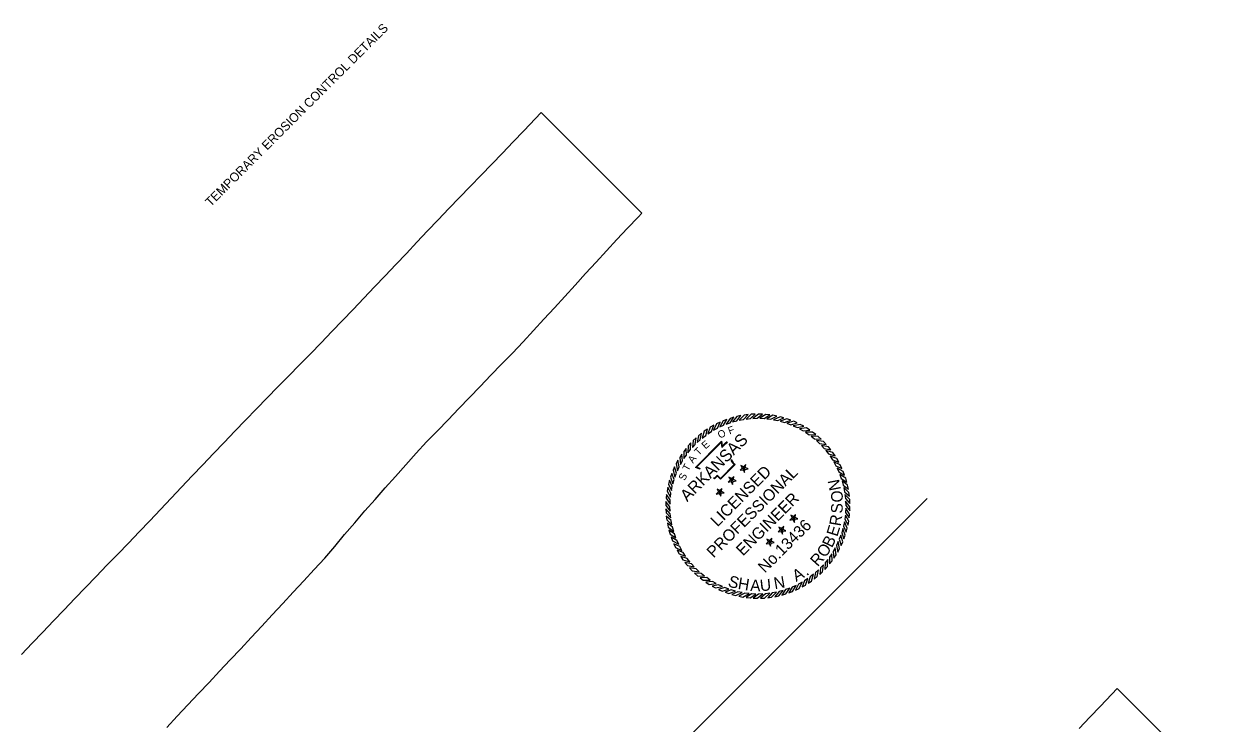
# Model space of a CAD drawing. Extents: x 1388120 to 1389841, y 1944102 to 1945760.
# Drawn here: x 1388980 to 1389753, y 1945307 to 1945760 of the extents above; entities that cross this region are included whole.
import ezdxf

# ---------------------------------------------------------------- set-up
doc = ezdxf.new("R2010")
doc.units = 0
for name, color, linetype in [('1', 7, 'Continuous'), ('G-ANNO-SYMB', 7, 'Continuous'), ('R_NO PLOT', 7, 'Continuous')]:
    doc.layers.add(name, color=color, linetype=linetype)

msp = doc.modelspace()

# ---------------------------------------------------------------- linework, layer by layer
at = {"layer": '1'}
msp.add_line((1389352.45, 1945239.6), (1389565.28, 1945452.44), dxfattribs=at)
at = {"layer": 'G-ANNO-SYMB'}
for points in [[(1389435.62, 1945503.65), (1389433.22, 1945502.74), (1389430.97, 1945498.76), (1389433.49, 1945499.9)], [(1389440.09, 1945505.05), (1389437.63, 1945504.33), (1389435.07, 1945500.54), (1389437.68, 1945501.48)], [(1389444.65, 1945506.1), (1389442.14, 1945505.57), (1389439.3, 1945501.99), (1389441.97, 1945502.72)], [(1389449.29, 1945506.78), (1389446.74, 1945506.45), (1389443.63, 1945503.11), (1389446.35, 1945503.63)], [(1389453.96, 1945507.1), (1389451.4, 1945506.97), (1389448.03, 1945503.88), (1389450.78, 1945504.18)], [(1389458.65, 1945507.05), (1389456.08, 1945507.12), (1389452.48, 1945504.3), (1389455.25, 1945504.39)], [(1389463.31, 1945506.63), (1389460.76, 1945506.9), (1389456.95, 1945504.38), (1389459.72, 1945504.25)], [(1389467.93, 1945505.85), (1389465.41, 1945506.32), (1389461.41, 1945504.1), (1389464.16, 1945503.76)], [(1389472.47, 1945504.7), (1389470, 1945505.37), (1389465.84, 1945503.48), (1389468.55, 1945502.92)], [(1389476.91, 1945503.21), (1389474.5, 1945504.07), (1389470.2, 1945502.51), (1389472.86, 1945501.73)], [(1389481.22, 1945501.37), (1389478.88, 1945502.42), (1389474.47, 1945501.2), (1389477.07, 1945500.22)], [(1389419.24, 1945494.7), (1389417.24, 1945493.09), (1389416.33, 1945488.61), (1389418.38, 1945490.48)], [(1389423.05, 1945497.42), (1389420.94, 1945495.97), (1389419.68, 1945491.57), (1389421.87, 1945493.27)], [(1389427.07, 1945499.82), (1389424.85, 1945498.54), (1389423.25, 1945494.26), (1389425.56, 1945495.78)], [(1389431.27, 1945501.9), (1389428.95, 1945500.8), (1389427.02, 1945496.66), (1389429.45, 1945498)], [(1389485.37, 1945499.2), (1389483.12, 1945500.43), (1389478.63, 1945499.56), (1389481.14, 1945498.38)], [(1389489.34, 1945496.71), (1389487.19, 1945498.11), (1389482.65, 1945497.59), (1389485.06, 1945496.22)], [(1389493.1, 1945493.92), (1389491.07, 1945495.48), (1389486.5, 1945495.32), (1389488.79, 1945493.76)], [(1389412.29, 1945488.42), (1389410.57, 1945486.52), (1389410.37, 1945481.95), (1389412.11, 1945484.12)], [(1389415.64, 1945491.7), (1389413.78, 1945489.94), (1389413.22, 1945485.4), (1389415.12, 1945487.42)], [(1389496.63, 1945490.84), (1389494.73, 1945492.56), (1389490.16, 1945492.76), (1389492.32, 1945491.02)], [(1389499.91, 1945487.49), (1389498.15, 1945489.35), (1389493.61, 1945489.91), (1389495.63, 1945488.01)], [(1389406.42, 1945481.13), (1389405.02, 1945478.99), (1389405.54, 1945474.44), (1389406.91, 1945476.85)], [(1389409.21, 1945484.89), (1389407.65, 1945482.86), (1389407.81, 1945478.29), (1389409.36, 1945480.59)], [(1389502.91, 1945483.89), (1389501.3, 1945485.89), (1389496.82, 1945486.8), (1389498.69, 1945484.75)], [(1389505.62, 1945480.07), (1389504.18, 1945482.19), (1389499.78, 1945483.45), (1389501.48, 1945481.26)], [(1389508.03, 1945476.05), (1389506.75, 1945478.28), (1389502.47, 1945479.88), (1389503.99, 1945477.56)], [(1389401.76, 1945473.02), (1389400.71, 1945470.67), (1389401.93, 1945466.27), (1389402.91, 1945468.86)], [(1389403.93, 1945477.17), (1389402.7, 1945474.91), (1389403.57, 1945470.43), (1389404.75, 1945472.93)], [(1389446.58, 1945471.97), (1389445.55, 1945472.14), (1389444.15, 1945470.74), (1389446.11, 1945471.05)], [(1389446.58, 1945471.97), (1389446.42, 1945473), (1389444.65, 1945473.9), (1389445.55, 1945472.14)], [(1389446.58, 1945471.97), (1389446.11, 1945471.05), (1389447.01, 1945469.28), (1389447.32, 1945471.24)], [(1389446.58, 1945471.97), (1389447.51, 1945472.45), (1389447.82, 1945474.4), (1389446.42, 1945473)], [(1389446.58, 1945471.97), (1389447.32, 1945471.24), (1389449.28, 1945471.55), (1389447.51, 1945472.45)], [(1389510.11, 1945471.86), (1389509.01, 1945474.18), (1389504.87, 1945476.11), (1389506.2, 1945473.68)], [(1389511.86, 1945467.51), (1389510.94, 1945469.91), (1389506.96, 1945472.16), (1389508.1, 1945469.63)], [(1389398.42, 1945464.27), (1389397.75, 1945461.79), (1389399.65, 1945457.63), (1389400.21, 1945460.34)], [(1389399.92, 1945468.71), (1389399.06, 1945466.29), (1389400.62, 1945461.99), (1389401.39, 1945464.66)], [(1389438.87, 1945464.26), (1389437.84, 1945464.42), (1389436.44, 1945463.02), (1389438.4, 1945463.33)], [(1389438.87, 1945464.26), (1389438.71, 1945465.29), (1389436.94, 1945466.19), (1389437.84, 1945464.42)], [(1389438.87, 1945464.26), (1389438.4, 1945463.33), (1389439.3, 1945461.57), (1389439.61, 1945463.52)], [(1389438.87, 1945464.26), (1389439.8, 1945464.73), (1389440.11, 1945466.69), (1389438.71, 1945465.29)], [(1389438.87, 1945464.26), (1389439.61, 1945463.52), (1389441.56, 1945463.83), (1389439.8, 1945464.73)], [(1389513.26, 1945463.04), (1389512.53, 1945465.5), (1389508.74, 1945468.06), (1389509.68, 1945465.45)], [(1389514.3, 1945458.47), (1389513.77, 1945460.98), (1389510.2, 1945463.83), (1389510.93, 1945461.16)], [(1389397.28, 1945459.72), (1389396.81, 1945457.2), (1389399.03, 1945453.2), (1389399.37, 1945455.95)], [(1389431.16, 1945456.55), (1389430.13, 1945456.71), (1389428.73, 1945455.31), (1389430.68, 1945455.62)], [(1389431.16, 1945456.55), (1389430.99, 1945457.57), (1389429.23, 1945458.47), (1389430.13, 1945456.71)], [(1389431.16, 1945456.55), (1389430.68, 1945455.62), (1389431.58, 1945453.85), (1389431.89, 1945455.81)], [(1389431.16, 1945456.55), (1389432.08, 1945457.02), (1389432.39, 1945458.98), (1389430.99, 1945457.57)], [(1389431.16, 1945456.55), (1389431.89, 1945455.81), (1389433.85, 1945456.12), (1389432.08, 1945457.02)], [(1389514.98, 1945453.84), (1389514.66, 1945456.38), (1389511.31, 1945459.5), (1389511.83, 1945456.78)], [(1389396.08, 1945450.44), (1389396.01, 1945447.88), (1389398.82, 1945444.27), (1389398.74, 1945447.04)], [(1389396.5, 1945455.11), (1389396.23, 1945452.56), (1389398.75, 1945448.74), (1389398.88, 1945451.51)], [(1389515.3, 1945449.17), (1389515.17, 1945451.73), (1389512.08, 1945455.1), (1389512.39, 1945452.34)], [(1389515.25, 1945444.48), (1389515.33, 1945447.05), (1389512.51, 1945450.65), (1389512.6, 1945447.88)], [(1389396.03, 1945445.76), (1389396.16, 1945443.19), (1389399.25, 1945439.82), (1389398.95, 1945442.58)], [(1389396.35, 1945441.08), (1389396.68, 1945438.54), (1389400.02, 1945435.42), (1389399.5, 1945438.14)], [(1389478.89, 1945439.67), (1389478.72, 1945440.7), (1389476.96, 1945441.6), (1389477.86, 1945439.83)], [(1389478.89, 1945439.67), (1389479.81, 1945440.14), (1389480.12, 1945442.1), (1389478.72, 1945440.7)], [(1389514.05, 1945435.2), (1389514.53, 1945437.72), (1389512.31, 1945441.72), (1389511.96, 1945438.97)], [(1389514.84, 1945439.82), (1389515.11, 1945442.37), (1389512.59, 1945446.18), (1389512.46, 1945443.41)], [(1389397.03, 1945436.45), (1389397.56, 1945433.94), (1389401.14, 1945431.09), (1389400.41, 1945433.76)], [(1389471.17, 1945431.96), (1389471.01, 1945432.99), (1389469.24, 1945433.89), (1389470.14, 1945432.12)], [(1389471.17, 1945431.96), (1389472.1, 1945432.43), (1389472.41, 1945434.39), (1389471.01, 1945432.99)], [(1389478.89, 1945439.67), (1389477.86, 1945439.83), (1389476.46, 1945438.43), (1389478.41, 1945438.74)], [(1389478.89, 1945439.67), (1389478.41, 1945438.74), (1389479.31, 1945436.98), (1389479.62, 1945438.93)], [(1389478.89, 1945439.67), (1389479.62, 1945438.93), (1389481.58, 1945439.24), (1389479.81, 1945440.14)], [(1389511.42, 1945426.22), (1389512.28, 1945428.63), (1389510.71, 1945432.93), (1389509.94, 1945430.27)], [(1389512.91, 1945430.65), (1389513.58, 1945433.13), (1389511.68, 1945437.29), (1389511.12, 1945434.58)], [(1389398.08, 1945431.88), (1389398.8, 1945429.42), (1389402.59, 1945426.86), (1389401.65, 1945429.47)], [(1389399.48, 1945427.41), (1389400.39, 1945425.01), (1389404.37, 1945422.76), (1389403.23, 1945425.29)], [(1389463.46, 1945424.24), (1389463.29, 1945425.27), (1389461.53, 1945426.17), (1389462.43, 1945424.41)], [(1389463.46, 1945424.24), (1389464.39, 1945424.72), (1389464.7, 1945426.67), (1389463.29, 1945425.27)], [(1389471.17, 1945431.96), (1389470.14, 1945432.12), (1389468.74, 1945430.72), (1389470.7, 1945431.03)], [(1389471.17, 1945431.96), (1389470.7, 1945431.03), (1389471.6, 1945429.26), (1389471.91, 1945431.22)], [(1389471.17, 1945431.96), (1389471.91, 1945431.22), (1389473.86, 1945431.53), (1389472.1, 1945432.43)], [(1389509.58, 1945421.91), (1389510.63, 1945424.25), (1389509.4, 1945428.65), (1389508.42, 1945426.06)], [(1389401.22, 1945423.06), (1389402.32, 1945420.75), (1389406.47, 1945418.81), (1389405.13, 1945421.24)], [(1389403.31, 1945418.87), (1389404.58, 1945416.64), (1389408.87, 1945415.04), (1389407.34, 1945417.36)], [(1389463.46, 1945424.24), (1389462.43, 1945424.41), (1389461.03, 1945423.01), (1389462.98, 1945423.32)], [(1389463.46, 1945424.24), (1389462.98, 1945423.32), (1389463.88, 1945421.55), (1389464.19, 1945423.51)], [(1389463.46, 1945424.24), (1389464.19, 1945423.51), (1389466.15, 1945423.82), (1389464.39, 1945424.72)], [(1389504.92, 1945413.79), (1389506.32, 1945415.94), (1389505.8, 1945420.48), (1389504.43, 1945418.07)], [(1389507.41, 1945417.76), (1389508.63, 1945420.01), (1389507.76, 1945424.5), (1389506.58, 1945421.99)], [(1389405.71, 1945414.85), (1389407.16, 1945412.73), (1389411.56, 1945411.47), (1389409.86, 1945413.66)], [(1389408.42, 1945411.03), (1389410.03, 1945409.03), (1389414.51, 1945408.12), (1389412.65, 1945410.17)], [(1389499.04, 1945406.5), (1389500.76, 1945408.4), (1389500.96, 1945412.97), (1389499.23, 1945410.81)], [(1389502.12, 1945410.03), (1389503.69, 1945412.06), (1389503.53, 1945416.63), (1389501.97, 1945414.34)], [(1389411.43, 1945407.43), (1389413.19, 1945405.57), (1389417.73, 1945405.01), (1389415.71, 1945406.91)], [(1389414.7, 1945404.09), (1389416.61, 1945402.37), (1389421.18, 1945402.17), (1389419.01, 1945403.9)], [(1389488.28, 1945397.5), (1389490.4, 1945398.95), (1389491.66, 1945403.35), (1389489.47, 1945401.65)], [(1389492.1, 1945400.22), (1389494.1, 1945401.83), (1389495.01, 1945406.31), (1389492.96, 1945404.44)], [(1389495.69, 1945403.22), (1389497.56, 1945404.98), (1389498.12, 1945409.52), (1389496.22, 1945407.5)], [(1389418.23, 1945401.01), (1389420.27, 1945399.44), (1389424.84, 1945399.6), (1389422.54, 1945401.16)], [(1389421.99, 1945398.21), (1389424.14, 1945396.81), (1389428.69, 1945397.33), (1389426.28, 1945398.7)], [(1389425.96, 1945395.72), (1389428.21, 1945394.49), (1389432.7, 1945395.37), (1389430.19, 1945396.55)], [(1389430.11, 1945393.55), (1389432.45, 1945392.5), (1389436.86, 1945393.72), (1389434.27, 1945394.7)], [(1389471.25, 1945389.87), (1389473.71, 1945390.59), (1389476.27, 1945394.39), (1389473.66, 1945393.45)], [(1389475.72, 1945391.27), (1389478.11, 1945392.19), (1389480.37, 1945396.17), (1389477.84, 1945395.02)], [(1389480.06, 1945393.02), (1389482.38, 1945394.12), (1389484.31, 1945398.26), (1389481.89, 1945396.93)], [(1389484.26, 1945395.1), (1389486.49, 1945396.38), (1389488.09, 1945400.66), (1389485.77, 1945399.14)], [(1389434.42, 1945391.71), (1389436.84, 1945390.85), (1389441.13, 1945392.41), (1389438.47, 1945393.19)], [(1389438.86, 1945390.22), (1389441.34, 1945389.55), (1389445.5, 1945391.44), (1389442.78, 1945392.01)], [(1389443.4, 1945389.08), (1389445.93, 1945388.6), (1389449.92, 1945390.82), (1389447.17, 1945391.17)], [(1389448.02, 1945388.29), (1389450.57, 1945388.02), (1389454.39, 1945390.54), (1389451.62, 1945390.67)], [(1389452.69, 1945387.88), (1389455.25, 1945387.8), (1389458.86, 1945390.62), (1389456.09, 1945390.53)], [(1389457.37, 1945387.83), (1389459.93, 1945387.95), (1389463.31, 1945391.04), (1389460.55, 1945390.74)], [(1389462.05, 1945388.14), (1389464.59, 1945388.47), (1389467.71, 1945391.82), (1389464.99, 1945391.3)], [(1389466.68, 1945388.83), (1389469.19, 1945389.35), (1389472.04, 1945392.93), (1389469.36, 1945392.2)]]:
    msp.add_lwpolyline(points, close=True, dxfattribs=at)
for points in [[(1389418.29, 1945471.32), (1389415.18, 1945472.47), (1389432.18, 1945489.49), (1389432.55, 1945486.28), (1389433.69, 1945487.46), (1389434.64, 1945488.43), (1389435.71, 1945489.29)], [(1389418.42, 1945471.68), (1389415.87, 1945472.62), (1389431.89, 1945488.66), (1389432.26, 1945485.44), (1389433.96, 1945487.19), (1389434.9, 1945488.15), (1389435.95, 1945489)], [(1389438.77, 1945477.54), (1389438.72, 1945477.01), (1389438.98, 1945476.56), (1389439.76, 1945475.59), (1389440.94, 1945474.41), (1389431.44, 1945464.91), (1389429.85, 1945466.5), (1389429.5, 1945466.85), (1389429, 1945466.58), (1389427.64, 1945465.23), (1389427.04, 1945465.36)], [(1389438.39, 1945477.58), (1389438.33, 1945476.93), (1389438.66, 1945476.35), (1389439.48, 1945475.33), (1389440.4, 1945474.41), (1389431.44, 1945465.45), (1389430.12, 1945466.77), (1389429.57, 1945467.32), (1389428.77, 1945466.89), (1389427.52, 1945465.65), (1389427.12, 1945465.73)]]:
    msp.add_lwpolyline(points, dxfattribs=at)
at = {"layer": 'R_NO PLOT'}
for points in [[(1389380.5, 1945637.22), (1389315.29, 1945702.43), (1389304.1, 1945690.63), (1389297.21, 1945683.38), (1389290.27, 1945676.18), (1389283.33, 1945668.98), (1389276.38, 1945661.79), (1389269.43, 1945654.6), (1389262.48, 1945647.4), (1389255.56, 1945640.19), (1389248.65, 1945632.96), (1389241.73, 1945625.74), (1389234.87, 1945618.46), (1389228.02, 1945611.18), (1389221.13, 1945603.93), (1389214.23, 1945596.7), (1389207.33, 1945589.46), (1389200.45, 1945582.19), (1389193.57, 1945574.94), (1389186.63, 1945567.73), (1389179.71, 1945560.52), (1389172.79, 1945553.3), (1389165.84, 1945546.11), (1389158.88, 1945538.93), (1389151.87, 1945531.79), (1389144.86, 1945524.66), (1389137.84, 1945517.53), (1389130.83, 1945510.4), (1389123.83, 1945503.25), (1389116.95, 1945496), (1389110.06, 1945488.75), (1389103.15, 1945481.52), (1389096.25, 1945474.28), (1389089.35, 1945467.04), (1389082.45, 1945459.8), (1389075.57, 1945452.55), (1389068.68, 1945445.3), (1389061.79, 1945438.04), (1389054.91, 1945430.79), (1389047.97, 1945423.59), (1389041.03, 1945416.39), (1389034.09, 1945409.19), (1389027.14, 1945402), (1389020.19, 1945394.81), (1389013.24, 1945387.61), (1389006.34, 1945380.37), (1388999.44, 1945373.14), (1388992.56, 1945365.88), (1388985.66, 1945358.64), (1388978.73, 1945351.43)], [(1389072.89, 1945304.04), (1389079.66, 1945311.4), (1389086.47, 1945318.73), (1389093.32, 1945326.01), (1389100.18, 1945333.28), (1389107.03, 1945340.57), (1389113.87, 1945347.87), (1389120.72, 1945355.15), (1389127.55, 1945362.46), (1389134.39, 1945369.75), (1389141.14, 1945377.13), (1389147.94, 1945384.46), (1389154.75, 1945391.79), (1389161.56, 1945399.11), (1389168.33, 1945406.47), (1389175.14, 1945413.79), (1389181.72, 1945421.33), (1389187.95, 1945429.2), (1389194.57, 1945436.7), (1389201.02, 1945444.37), (1389207.85, 1945451.67), (1389214.37, 1945459.26), (1389221.06, 1945466.7), (1389227.76, 1945474.13), (1389234.26, 1945481.74), (1389241.11, 1945489.03), (1389248.08, 1945496.2), (1389254.98, 1945503.44), (1389261.9, 1945510.65), (1389268.87, 1945517.83), (1389275.81, 1945525.03), (1389282.77, 1945532.21), (1389289.72, 1945539.4), (1389296.68, 1945546.59), (1389303.58, 1945553.82), (1389310.35, 1945561.19), (1389317.07, 1945568.6), (1389323.86, 1945575.93), (1389330.59, 1945583.33), (1389337.35, 1945590.7), (1389344.11, 1945598.07), (1389350.88, 1945605.44), (1389357.64, 1945612.81), (1389364.4, 1945620.17), (1389371.29, 1945627.42), (1389378.14, 1945634.71), (1389380.5, 1945637.22)], [(1389663.86, 1945303.48), (1389670.73, 1945310.74), (1389677.61, 1945318), (1389688.38, 1945329.34), (1389753.12, 1945264.6)]]:
    msp.add_lwpolyline(points, dxfattribs=at)

# ---------------------------------------------------------------- texts
at = {"layer": '1'}
msp.add_text('TEMPORARY EROSION CONTROL DETAILS', height=5.862, rotation=45, dxfattribs=at).set_placement((1389101.22, 1945641.07))
at = {"layer": 'G-ANNO-SYMB'}
for s, height, rotation, p in [('O', 4.75, 26.2218, (1389431.04, 1945491.09)), ('F', 4.75, 20.36282, (1389437.33, 1945493.85)), ('ARKANSAS', 7.747, 45, (1389409.92, 1945449.91)), ('E', 4.75, 41.67203, (1389421.74, 1945484.09)), ('A', 4.75, 53.67877, (1389413.68, 1945474.9)), ('T', 4.75, 46.47887, (1389417.34, 1945479.9)), ('T', 4.75, 61.90148, (1389410.67, 1945469.76)), ('LICENSED', 7.5, 45, (1389429.5, 1945433.73)), ('S', 4.75, 64.77256, (1389408.31, 1945463.57)), ('PROFESSIONAL', 7.5, 45, (1389427, 1945413.49)), ('N', 7.5, 101.10067, (1389509.53, 1945458.28)), ('O', 7.5, 89.77573, (1389510.62, 1945449.83)), ('ENGINEER', 7.5, 45, (1389445.98, 1945414.73)), ('S', 7.5, 88.48784, (1389510.5, 1945442.66)), ('R', 7.5, 80.65967, (1389509.23, 1945434.18)), ('No.13436', 7.47, 45, (1389460.29, 1945403.76)), ('E', 7.5, 72.83149, (1389507.09, 1945427.35)), ('B', 7.5, 63.88501, (1389503.65, 1945420.08)), ('O', 7.5, 56.42961, (1389499.46, 1945413.64)), ('R', 7.5, 48.22866, (1389494.38, 1945407.87)), ('S', 7.5, 343.16364, (1389435.81, 1945395.65)), ('N', 7.5, 9.93262, (1389466.65, 1945393.68)), ('A', 7.5, 28.09908, (1389480.44, 1945398.37)), ('.', 7.5, 36.30002, (1389487.2, 1945402.04)), ('H', 7.5, 350.61905, (1389442.38, 1945393.91)), ('A', 7.5, 358.44722, (1389450.59, 1945392.43)), ('U', 7.5, 5.90262, (1389457.36, 1945392.28))]:
    msp.add_text(s, height=height, rotation=rotation, dxfattribs=at).set_placement(p)

doc.saveas('drawing.dxf')
